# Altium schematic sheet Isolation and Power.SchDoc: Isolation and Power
size A3; CompanyName: Hitex GmbH; Address1: Greschbachstr. 12; Address2: 76229 Karlsruhe, Germany; Address3: www.hitex.com; DocumentNumber: 6; SheetNumber: 6; SheetTotal: 8; PageSetup: Record=PageOptions¦CenterHorizontal=True¦CenterVertical=True¦PrintScale=1.04¦XCorrection=1.00¦YCorrection=1.00¦PrintKind=0¦BorderSize=5000000¦LeftOffset=0¦BottomOffset=0¦Orientation=2¦PaperLength=1000¦PaperWidth=1000¦Scale=100¦PaperSource=7¦PrintQuality=1200¦MediaType=1¦DitherType=10¦PaperKind=A3¦PrintScaleMode=1
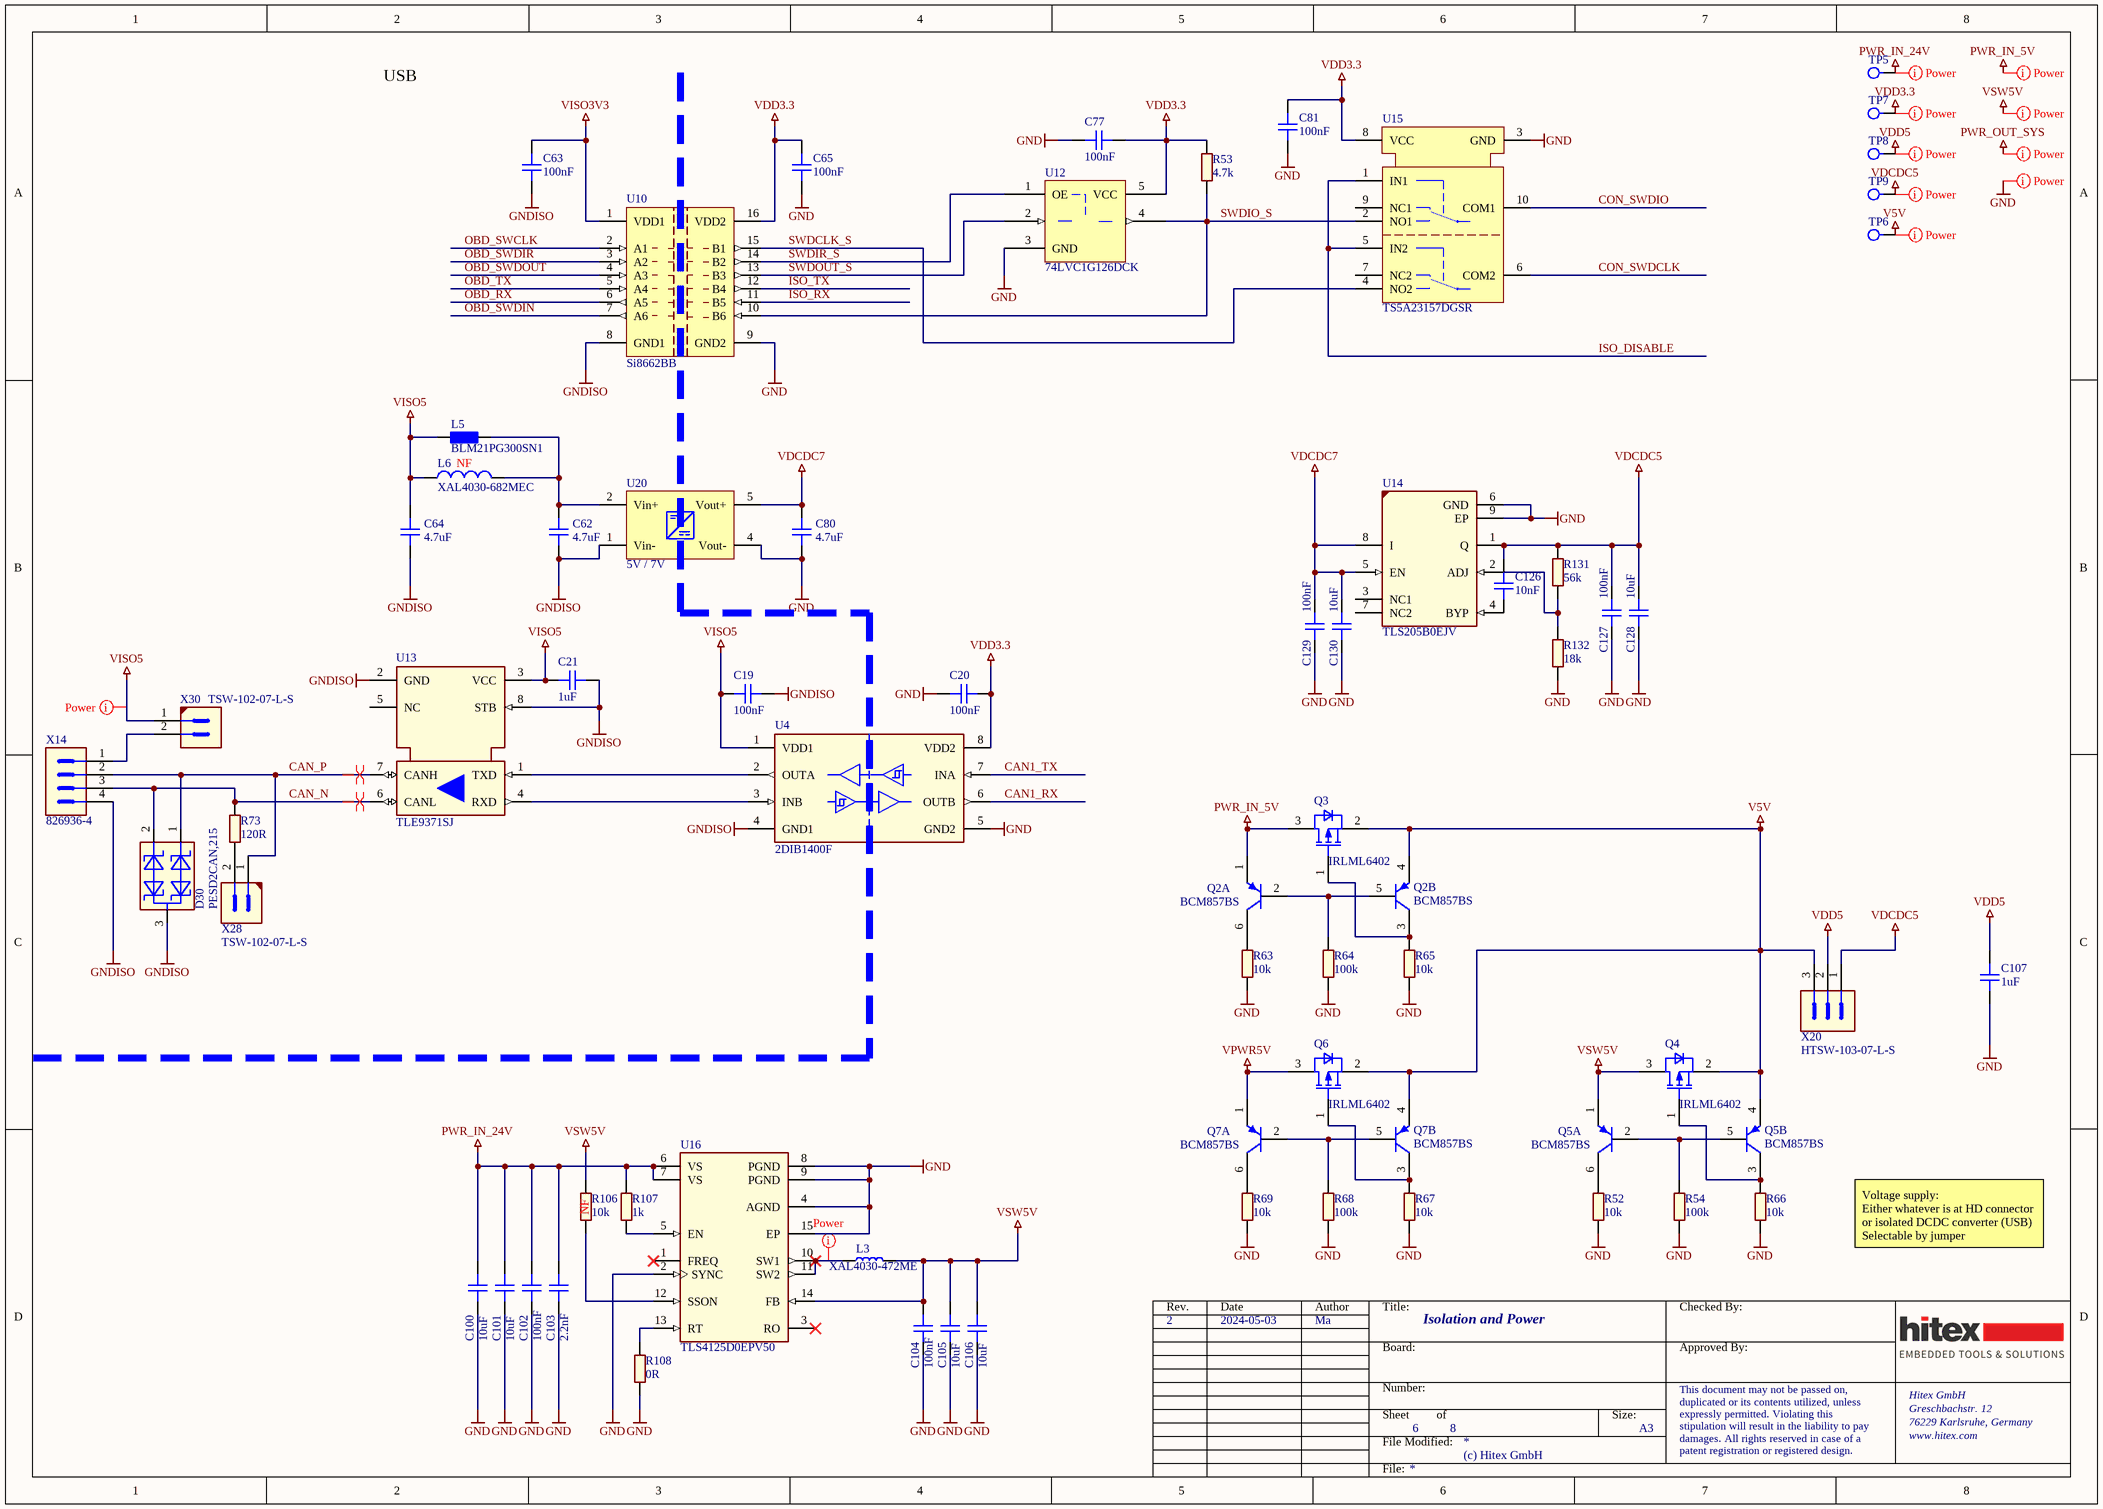
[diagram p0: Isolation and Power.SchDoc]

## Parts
C19  100nF  [CAPC1005X55N-0]
C20  100nF  [CAPC1005X55N-0]
C21  1uF  [CAPC1608X90N-1]
C62  4.7uF  [CAPC2013X145N-3]
C63  100nF  [CAPC1005X55N-0]
C64  4.7uF  [CAPC2013X145N-3]
C65  100nF  [CAPC1005X55N-0]
C77  100nF  [CAPC1005X55N-0]
C80  4.7uF  [CAPC2013X145N-3]
C81  100nF  [CAPC1005X55N-0]
C100  10uF  [CAPC3216X180N]
C101  10uF  [CAPC3216X180N]
C102  100nF  [CAPC1005X55N-0]
C103  2.2nF  [CAPC1005X55N-0]
C104  100nF  [CAPC1005X55N-0]
C105  10uF  [CAPC3216X180N]
C106  10uF  [CAPC3216X180N]
C107  1uF  [CAPC1608X90N-1]
C126  10nF  [CAPC1005X55N-0]
C127  100nF  [CAPC1005X60N]
C128  10uF  [CAPC3216X180N]
C129  100nF  [CAPC1005X55N-0]
C130  10uF  [CAPC3216X180N]
D30  PESD2CAN,215  [SOT95P230X110-3N]
L3  4.7uH  [XAL4030-472ME]  (value not drawn)
L5  BLM21PG300SN1  [INDC2009N]
L6  XAL4030-682MEC  [XFL4020]
Q2  BCM857BS  [SOT363-6M]  (parts A,B of 2)
Q3  IRLML6402  [SOT95P237X112-3N-2-V]
Q4  IRLML6402  [SOT95P237X112-3N-2-V]
Q5  BCM857BS  [SOT363-6M]  (parts A,B of 2)
Q6  IRLML6402  [SOT95P237X112-3N-2-V]
Q7  BCM857BS  [SOT363-6M]  (parts A,B of 2)
R52  10k  [RESC1005X40N]
R53  4.7k  [RESC1609X50N]
R54  100k  [RESC1005X40N]
R63  10k  [RESC1005X40N]
R64  100k  [RESC1005X40N]
R65  10k  [RESC1005X40N]
R66  10k  [RESC1005X40N]
R67  10k  [RESC1005X40N]
R68  100k  [RESC1005X40N]
R69  10k  [RESC1005X40N]
R73  120R  [RESC3216X60N]
R106  10k  [RESC1005X40N]
R107  1k  [RESC1005X40N]
R108  0R  [RESC1005X03N]
R131  56k  [RESC1005X40N]
R132  18k  [RESC1005X40N]
TP5  (no value)  [TP_RD_SMD_1MM]  (no BOM)
TP6  (no value)  [TP_RD_SMD_1MM]  (no BOM)
TP7  (no value)  [TP_RD_SMD_1MM]  (no BOM)
TP8  (no value)  [TP_RD_SMD_1MM]  (no BOM)
TP9  (no value)  [TP_RD_SMD_1MM]  (no BOM)
U4  2DIB1400F  [SOIC127P600X175-8N-22-V1]
U10  Si8662BB  [SOIC127P600-16N]
U12  74LVC1G126DCK  [SOT353-5N]
U13  TLE9371SJ  [SOIC127P602X173-8N]
U14  TLS205B0EJV  [SOIC127P600X170-9N-3-V1]
U15  TS5A23157DGSR  [VSSOP50P490X110-10N]
U16  TLS4125D0EPV50  [SOP65P600X115-15N]
U20  5V / 7V  [IES0205S05]
X14  826936-4  [CON-M-THT-826936-4]
X20  HTSW-103-07-L-S  [CON-M-THT-HTSW-103-07-L-S]
X28  TSW-102-07-L-S  [CON-M-THT-TSW-102-07-L-S]
X30  TSW-102-07-L-S  [CON-M-THT-TSW-102-07-L-S]

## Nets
GND: C20.2 C65.1 C77.1 C80.1 C81.1 C100.1 C101.1 C102.2 C103.1 C104.1 C105.1 C106.1 C107.1 C127.1 C128.1 C129.1 C130.1 R52.1 R54.2 R63.1 R64.2 R65.1 R66.1 R67.1 R68.2 R69.1 R108.1 R132.1 U4.5(GND2) U10.9(GND2) U12.3(GND) U14.6(GND) U14.9(EP) U15.3(GND) U16.2(SYNC) U16.4(AGND) U16.8(PGND) U16.9(PGND) U16.15(EP) U20.4(Vout-)
GNDISO: C19.2 C21.1 C62.1 C63.1 C64.1 D30.3(COMMON_CATHODE) U4.4(GND1) U10.8(GND1) U13.2(GND) U13.8(STB) U20.1(Vin-) X14.4
PWR_IN_5V: Q2.1(E1) Q3.3(DRAIN)
PWR_IN_24V: C100.2 C101.2 C102.1 C103.2 R107.2 TP5.1 U16.6(VS) U16.7(VS)
V5V: Q2.4(E2) Q3.2(SOURCE) Q4.2(SOURCE) Q5.4(E2) Q6.2(SOURCE) Q7.4(E2) TP6.1 X20.3
VDCDC5: C126.2 C127.2 C128.2 R131.2 TP9.1 U14.1(Q) X20.1
VDCDC7: C80.2 C129.2 C130.2 U14.5(EN) U14.8(I) U20.5(Vout+)
VDD3.3: C20.1 C65.2 C77.2 C81.2 R53.2 TP7.1 U4.8(VDD2) U10.16(VDD2) U12.5(VCC) U15.8(VCC)
VDD5: C107.2 TP8.1 X20.2
VISO3V3: C63.2 U10.1(VDD1)
VISO5: C19.1 C21.2 C64.2 L5.1 L6.1 U4.1(VDD1) U13.3(VCC) X30.1
VPWR5V: Q6.3(DRAIN) Q7.1(E1)
VSW5V: C104.2 C105.2 C106.2 L3.2 Q4.3(DRAIN) Q5.1(E1) R106.2 U16.14(FB)
CAN1_RX: U4.6(OUTB)
CAN1_TX: U4.7(INA)
CAN_N: D30.2(CATHODE2) R73.2 U13.6(CANL) X14.3
CAN_P: D30.1(CATHODE1) U13.7(CANH) X14.2 X28.1
CON_SWDCLK: U15.6(COM2)
CON_SWDIO: U15.10(COM1)
ISO_DISABLE: U15.1(IN1) U15.5(IN2)
ISO_RX: U10.11(B5)
ISO_TX: U10.12(B4)
OBD_RX: U10.6(A5)
OBD_SWCLK: U10.2(A1)
OBD_SWDIN: U10.7(A6)
OBD_SWDIR: U10.3(A2)
OBD_SWDOUT: U10.4(A3)
OBD_TX: U10.5(A4)
SWDCLK_S: U10.15(B1) U15.4(NO2)
SWDIO_S: R53.1 U10.10(B6) U12.4(Y) U15.2(NO1)
SWDIR_S: U10.14(B2) U12.1(OE)
SWDOUT_S: U10.13(B3) U12.2(A)
NetC62_2: C62.2 L5.2 L6.2 U20.2(Vin+)
NetC126_1: C126.1 U14.4(BYP)
NetL3_1: L3.1 U16.10(SW1) U16.11(SW2)
NetQ2_2: Q2.2(B1) Q2.5(B2) R64.1
NetQ2_3: Q2.3(C2) Q3.1(GATE) R65.2
NetQ2_6: Q2.6(C1) R63.2
NetQ4_1: Q4.1(GATE) Q5.3(C2) R66.2
NetQ5_2: Q5.2(B1) Q5.5(B2) R54.1
NetQ5_6: Q5.6(C1) R52.2
NetQ6_1: Q6.1(GATE) Q7.3(C2) R67.2
NetQ7_2: Q7.2(B1) Q7.5(B2) R68.1
NetQ7_6: Q7.6(C1) R69.2
NetR73_1: R73.1 X28.2
NetR106_1: R106.1 U16.12(SSON)
NetR107_1: R107.1 U16.5(EN)
NetR108_2: R108.2 U16.13(RT)
NetR131_1: R131.1 R132.2 U14.2(ADJ)
NetU4_2: U4.2(OUTA) U13.1(TXD)
NetU4_3: U4.3(INB) U13.4(RXD)
NetX14_1: X14.1 X30.2

Not connected (* = marked no-connect by the designer): U13 5(NC); U14 3(NC1) 7(NC2); U15 7(NC2) 9(NC1); U16 1(FREQ)* 3(RO)*

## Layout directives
net class Power: GND, NetL3_1, PWR_IN_5V, PWR_IN_24V, PWR_OUT_SYS, V5V, VDCDC5, VDD3.3, VDD5, VISO5, VSW5V
differential pair; differential pair class DIFF120R: CAN_N, CAN_P

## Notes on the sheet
- USB
- (near L6) NF
- (near R106) NF
- Voltage supply:
  Either whatever is at HD connector
  or isolated DCDC converter (USB)
  Selectable by jumper
- 2
- 2024-05-03
- Ma
- Labels drawn without touching a wire or pin: GND, PWR_IN_5V, PWR_OUT_SYS, VSW5V

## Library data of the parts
C19 C20 C63 C65 C77 C81 C102 C104 C129 = 310625: CAP / CERA / 100nF / 50V / 10% / X7R (EIA) / -55°C to 125°C / 0402(1005) / SMD / -; Multiple Parts: No; Legacy PartNumber: CAP01010920; Manufacturer: MuRata; Manufacturer Order Number: GRM155R71H104KE14D; Symbol Type: Capacitor; Single; Standard; 2 Pins; Alternate View: Yes; Article Number: 310625; Version Number: V01; Combined Parameters: TC:X7R (EIA);Tol.:-10%/+10%;Vdc:50V; QuickPick: 100nF / 50V / 10% / X7R (EIA) / 0402 (1005M); Type: Standard; Style: Single; Package Metric: 1005; Package Imperial: 0402; ComponentStatus: Released; PLMStatus: Active; HTX: 01.22.0596.0
C21 C107 = 668123: CAP / CERA / 1uF / 25V / 10% / X7R (EIA) / -55°C to 125°C / 0603(1608) / SMD / -; Multiple Parts: No; Manufacturer: Samsung; Manufacturer Order Number: CL10B105KA8NNNC; Symbol Type: Capacitor; Single; Standard; 2 Pins; Alternate View: Yes; Article Number: 668123; Version Number: V01; Combined Parameters: TC:X7R (EIA);Tol.:-10%/+10%;Vdc:25V; QuickPick: 1uF / 25V / 10% / X7R (EIA) / 0603 (1608); Type: Standard; Style: Single; Package Metric: 1608; Package Imperial: 0603; ComponentStatus: Released; PLMStatus: Active; HTX: 01.22.0270.0
C62 C64 C80 = 673682: CAP / CERA / 4.7uF / 25V / 20% / X7R (EIA) / -55°C to 125°C / 0805 / SMD / -; Multiple Parts: No; Manufacturer: Yageo; Manufacturer Order Number: CC0805MKX7R8BB475; Symbol Type: Capacitor; Single; Standard; 2 Pins; Alternate View: Yes; Article Number: 673682; Version Number: V00; Combined Parameters: TC:X7R (EIA);Tol.:-20%/+20%;Vdc:25V; QuickPick: 4.7uF / 25V / 20% / X7R (EIA) / 0805; Type: Standard; Style: Single; ComponentStatus: Released; PLMStatus: Active; HTX: 01.22.0436.0
C100 C101 C105 C106 C128 C130 = 282249: CAP / CERA / 10uF / 50V / 20% / X5R (EIA) / -55°C to 85°C / 1206(3216) / SMD / -; Multiple Parts: No; Manufacturer: MuRata; Manufacturer Order Number: GRM31CR61H106MA12L; Symbol Type: Capacitor; Single; Standard; 2 Pins; Alternate View: Yes; Article Number: 282249; Version Number: V01; Combined Parameters: TC:X5R (EIA);Tol.:-20%/+20%;Vdc:50V; QuickPick: 10uF / 50V / 20% / X5R (EIA) / 1206 (3216); Type: Standard; Style: Single; Package Metric: 3216; Package Imperial: 1206; ComponentStatus: Released; PLMStatus: Not Recommended For New Designs; HTX: 01.22.0647.0
C103 = 289386: CAP / CERA / 2.2nF / 50V / 20% / X7R (EIA) / -55°C to 125°C / 0402(1005) / SMD / -; Multiple Parts: No; Legacy PartNumber: CAP01006950; Manufacturer: MuRata; Manufacturer Order Number: GCM155R71H222MA37; Symbol Type: Capacitor; Single; Standard; 2 Pins; Alternate View: Yes; Article Number: 289386; Version Number: V01; Combined Parameters: TC:X7R (EIA);Tol.:-20%/+20%;Vdc:50V; QuickPick: 2.2nF / 50V / 20% / X7R (EIA) / CAPC1005X55N-0; Type: Standard; Style: Single; Automotive Qualified: AEC Q200; Package Metric: 1005; Package Imperial: 0402; ComponentStatus: Released; PLMStatus: Active; HTX: 01.22.0627.0
C126 = 264563: CAP / CERA / 10nF / 16V / 5% / X7R (EIA) / -55°C to 125°C / 0402(1005) / SMD / -; Multiple Parts: No; Legacy PartNumber: CAP01001706; Manufacturer: MuRata; Manufacturer Order Number: GRM155R71C103JA01; Symbol Type: Capacitor; Single; Standard; 2 Pins; Alternate View: Yes; Article Number: 264563; Version Number: V01; Combined Parameters: TC:X7R (EIA);Tol.:-5%/+5%;Vdc:16V; QuickPick: 10nF / 16V / 5% / X7R (EIA) / 0402 (1005); Type: Standard; Style: Single; Package Metric: 1005; Package Imperial: 0402; ComponentStatus: Released; PLMStatus: Not Recommended For New Designs; HTX: 01.22.0592.0
C127 = 507459: CAP / CERA / 100nF / 50V / 10% / X7R (EIA) / -55°C to 125°C / 0402(1005) / SMD / -; Multiple Parts: No; Manufacturer: TDK Corporation; Manufacturer Order Number: C1005X7R1H104K050BE; Symbol Type: Capacitor; Single; Standard; 2 Pins; Alternate View: Yes; Article Number: 507459; Version Number: V01; Combined Parameters: TC:X7R (EIA);Tol.:-10%/+10%;Vdc:50V; QuickPick: 100nF / 50V / 10% / X7R (EIA) / 0402 (1005); Type: Standard; Style: Single; Package Metric: 1005; Package Imperial: 0402; ComponentStatus: Released; PLMStatus: Active; HTX: 01.22.0596.0
D30 = 527432: CAN bus ESD protection diode; Multiple Parts: No; Manufacturer: Nexperia; Symbol type: Bi-Directional Transient Voltage Suppressor Diode, 1 Cathode 2 Cathode 3 Common Cathode; Article Number: 527432; Version Number: V01; Combined Parameters: Vf:-;If:-;Ur:24V;Ir:-;Pmax:-; QuickPick: TVS Diode / SOT23 (TO-236AB); Type: TVS Diode; Style: Single; Automotive Qualified: AEC Q101; ComponentStatus: Released; PLMStatus: Active; Second Source allowed: Yes; Voltage DC (max): na; HTX: 00.40.0090.0
L3 = 325876: IND / STD / 4.7uH / 5.1A / 20% / -40°C to 125°C / 44.1R / SMD Type / Inductor,Chip;4.00mm L X 4.00mm W X 3.10mm H / SMD / -; Multiple Parts: No; Legacy PartNumber: IND00702665; Manufacturer: Coilcraft; Symbol Type: Inductor; Single; Standard; 2 Pins; Alternate View: Yes; Article Number: 325876; Version Number: V01; Combined Parameters: Tol.:-20%/+20%;Rdc:44.1R;Idc:5.1A;Fres:36MHz; QuickPick: 4.7uH / Standard / SMD Type; Type: Standard; Style: Single; Automotive Qualified: AEC Q200; ComponentStatus: Released; PLMStatus: Active; Voltage DC (max): na; HTX: 01.30.0268.0
L5 = BLM21PG300SN1: FERRITE, SMD, 30 OHM, 4000mA, 0805; PartNumber: 01.30.0266.0; Manufacturer: Murata; Designer: Ma; CheckOrientation: false
L6 = XAL4030-682MEC: 2.2uH - Isat 5.6A; PartNumber: 01.30.0326.0; Manufacturer: Coilcraft; Designer: Kr; CheckOrientation: false
Q2 Q5 Q7 = BCM8575BS,115: Dual PNP/PNP, Vceo -45V, Ic -100mA, hFE 290, AEC-Q; PartNumber: 00.94.0374.0; Manufacturer: Nexperia; ManufacturerPartNo: BCM857BS,115; Designer: Th; CheckOrientation: ´True
Q3 Q4 Q6 = 400833: HEXFET P-Channel Power MOSFET, 20V, 3.7A; Manufacturer: Infineon Technologies; Symbol Type: Insulated-Gate Field-Effect Transistor (IGFET), P-Channel, Enhancement,  Body Diode, Pin 1 Gate, 2 Source, 3 Drain, 3 Pins; Article Number: 400833; Version Number: V01; Legacy DeviceID: IFX_IRLML6402; Combined Parameters: P-Channel;Uds:-20V;Id:-3.7A;Rds:65mR;P:1.3W; QuickPick: P-Channel / 1.3W / -3.7A / -20V / PG-SOT23-3-901; Style: Single; Automotive Qualified: No; ComponentStatus: Released; PLMStatus: Active; Second Source allowed: Yes; Voltage DC (max): na; HTX: 00.94.0102.0
R52 R63 R65-R67 R69 R106 = 342167: RES / STD / 10k / 63mW / 1% / 100ppm/K / -55°C to 155°C / 0402 / SMD / -; Multiple Parts: No; Legacy PartNumber: RES01800457; Manufacturer: Vishay; Manufacturer Order Number: CRCW040210K0FK; Symbol Type: Resistor; Single; Standard; 2 Pins; Alternate View: Yes; Article Number: 342167; Version Number: V01; Combined Parameters: TCR:100ppm/K;Tol.:-1%/+1%;Vdc:50V;Idc:-;P:63mW; QuickPick: 10k / 1% / 0.063 / 0402; Style: Single; Automotive Qualified: AEC Q200; ComponentStatus: Released; PLMStatus: Active; Voltage DC (max): 50V; HTX: 01.02.0703.0
R53 = 345982: RES / STD / 4.7k / 100mW / 1% / 100ppm/K / -55°C to 155°C / 0603(1608) / SMD / -; Multiple Parts: No; Legacy PartNumber: RES01801219; Manufacturer: Vishay; Manufacturer Order Number: CRCW06034K70FK; Symbol Type: Resistor; Single; Standard; 2 Pins; Alternate View: Yes; Article Number: 345982; Version Number: V01; Combined Parameters: TCR:100ppm/K;Tol.:-1%/+1%;Vdc:75V;Idc:-;P:100mW; QuickPick: 4.7k / 1% / 0.1 / 0603 (1608); Style: Single; Automotive Qualified: AEC Q200; Package Metric: 1608; Package Imperial: 0603; ComponentStatus: Released; PLMStatus: Active; Voltage DC (max): 75V; HTX: 01.02.0437.0
R54 R64 R68 = 342737: RES / STD / 100k / 63mW / 1% / 100ppm/K / -55°C to 155°C / 0402 / SMD / -; Multiple Parts: No; Legacy PartNumber: RES01800571; Manufacturer: Vishay; Manufacturer Order Number: CRCW0402100KFK; Symbol Type: Resistor; Single; Standard; 2 Pins; Alternate View: Yes; Article Number: 342737; Version Number: V01; Combined Parameters: TCR:100ppm/K;Tol.:-1%/+1%;Vdc:50V;Idc:-;P:63mW; QuickPick: 100k / 1% / 0.063 / 0402; Style: Single; Automotive Qualified: AEC Q200; ComponentStatus: Released; PLMStatus: Active; Voltage DC (max): 50V; HTX: 01.02.0716.0
R73 = 353082: RES / STD / 120R / 250mW / 1% / 100ppm/K / -55°C to 155°C / 1206(3216) / SMD / -; Multiple Parts: No; Legacy PartNumber: RES01802637; Manufacturer: Vishay; Manufacturer Order Number: CRCW1206120RFK; Symbol Type: Resistor; Single; Standard; 2 Pins; Alternate View: Yes; Article Number: 353082; Version Number: V01; Combined Parameters: TCR:100ppm/K;Tol.:-1%/+1%;Vdc:200V;Idc:-;P:250mW; QuickPick: 120R / 1% / 0.25 / 1206 (3216); Style: Single; Automotive Qualified: AEC Q200; Package Metric: 3216; Package Imperial: 1206; ComponentStatus: Released; PLMStatus: Active; Voltage DC (max): 200V; HTX: 01.02.0102.0
R107 = 341597: RES / STD / 1k / 63mW / 1% / 100ppm/K / -55°C to 155°C / 0402 / SMD / -; Multiple Parts: No; Legacy PartNumber: RES01800343; Manufacturer: Vishay; Manufacturer Order Number: CRCW04021K00FK; Symbol Type: Resistor; Single; Standard; 2 Pins; Alternate View: Yes; Article Number: 341597; Version Number: V01; Combined Parameters: TCR:100ppm/K;Tol.:-1%/+1%;Vdc:50V;Idc:-;P:63mW; QuickPick: 1k / 1% / 0.063 / 0402; Style: Single; Automotive Qualified: AEC Q200; ComponentStatus: Released; PLMStatus: Active; Voltage DC (max): 50V; HTX: 01.02.0701.0
R108 = 327372: RES / STD / 0R / 63mW / 0R / 0ppm/K / -55°C to 155°C / 0402(1005) / SMD / -; Multiple Parts: No; Legacy PartNumber: RES00000001; Manufacturer: Yageo; Manufacturer Order Number: RC0402JR-070RL; Symbol Type: Resistor; Single; Standard; 2 Pins; Alternate View: Yes; Article Number: 327372; Version Number: V01; Combined Parameters: TCR:0ppm/K;Tol.:-0R/+0R;Vdc:50V;Idc:1A;P:63mW; QuickPick: 0R / 0R / 0.063 / 0402 (1005); Style: Single; Package Metric: 1005; Package Imperial: 0402; ComponentStatus: Released; PLMStatus: Active; Voltage DC (max): 50V; HTX: 01.02.0902.0
R131 = 342592: RES / STD / 56k / 63mW / 1% / 100ppm/K / -55°C to 155°C / 0402(1005) / SMD / -; Multiple Parts: No; Legacy PartNumber: RES01800542; Manufacturer: Vishay; Manufacturer Order Number: CRCW040256K0FK; Symbol Type: Resistor; Single; Standard; 2 Pins; Alternate View: Yes; Article Number: 342592; Version Number: V01; Combined Parameters: TCR:100ppm/K;Tol.:-1%/+1%;Vdc:50V;Idc:-;P:63mW; QuickPick: 56k / 1% / 0.063 / 0402 (1005); Style: Single; Automotive Qualified: AEC Q200; Package Metric: 1005; Package Imperial: 0402; ComponentStatus: Released; PLMStatus: Active; Voltage DC (max): 50V; HTX: 01.02.0770.0
R132 = 342302: RES / STD / 18k / 63mW / 1% / 100ppm/K / -55°C to 155°C / 0402(1005) / SMD / -; Multiple Parts: No; Legacy PartNumber: RES01800484; Manufacturer: Vishay; Manufacturer Order Number: CRCW040218K0FK; Symbol Type: Resistor; Single; Standard; 2 Pins; Alternate View: Yes; Article Number: 342302; Version Number: V01; Combined Parameters: TCR:100ppm/K;Tol.:-1%/+1%;Vdc:50V;Idc:-;P:63mW; QuickPick: 18k / 1% / 0.063 / 0402 (1005); Style: Single; Automotive Qualified: AEC Q200; Package Metric: 1005; Package Imperial: 0402; ComponentStatus: Released; PLMStatus: Active; Voltage DC (max): 50V; HTX: 01.02.0757.0
TP5-TP9 = Testpad_Round: Testpad SMD / THT; PartNumber: -NoPartNumber-; Designer: Ma; CheckOrientation: false
U4 = 2DIB1400F: Robust Digital Isolator, 1 Forward 1 Reverse Channel Configuration; Manufacturer: Infineon Technologies; HTX: 00.81.0361.0
U10 = Si8662BB-B-IS1: 6-Ch Digital Isolator (4xIn / 2xOut), 150Mbit/s, 2500Vrms, SOIC-16, active low; Manufacturer: Skyworks Solutions Inc.; PartNumber: 00.81.0252.0; Designer: Ma; CheckOrientation: true
U12 = 74LVC1G126DCK: Single Gate Buffer/Driver, OE high active, 1.65V - 5.5V, SC70-5; PartNumber: 00.29.0112.0; Manufacturer: Texas Instruments; ManufacturerPartNo: SN74LVC1G126DCKR; Designer: Ma; Note: NXP 74LVC1G126GW; CheckOrientation: false
U13 = 694499: CAN signal improvement transceiver; Manufacturer: Infineon Technologies; Alternate View: No; Symbol Type: High Speed CAN FD Transceiver; Article Number: 694499; Version Number: V01; Legacy DeviceID: IFX_TLE9371SJ; Combined Parameters: Automotive Interface/Transceiver;Vdc min/max:4.75V/5.25V;Iout:5mA;Fmax:-; QuickPick: PG-DSO-8-80; Automotive Qualified: AEC Q100; ComponentStatus: Released; PLMStatus: Active; Second Source allowed: Yes; Voltage DC (max): na; HTX: 00.40.0396.0
U14 = 592428: Micropower, low noise, low dropout voltage regulator, Designed for use in battery-powered systems, the low quiescent current of 30 µA makes it an ideal choice; Multiple Parts: No; Manufacturer: Infineon Technologies; Symbol Type: Low Dropout, Low Noise, Linear Voltage Post Regulator, 3.3V, 500 mA; Article Number: 592428; Version Number: V01; Legacy DeviceID: IFX_TLS205B0EJV; Combined Parameters: Linear - -;Vo:1.19V to 1.25V; QuickPick: Linear / PG-DSO-8-52; Automotive Qualified: Yes; ComponentStatus: Released; PLMStatus: Active; Voltage DC (max): na; HTX: 00.40.0359.0
U15 = TS5A23157DGSR: TS5A23157DGSR, 1.8V-5V, 2:1 (SPDT), 2-channel analog switch, 10R; PartNumber: 00.30.0133.0; Manufacturer: Texas Instruments; Designer: Th; CheckOrientation: true
U16 = 513815: OPTIREG Switcher 2.8 MHz Synchronous Step-Down Regulator, 2.5A, 5V, Input voltage 3.7 V to 35 V; Manufacturer: Infineon Technologies; Alternate View: No; Article Number: 513815; Version Number: V01; Legacy DeviceID: IFX_TLS4125D0EPV50; Combined Parameters: Switched DC/DC -;Vo:- to 5V; QuickPick: Switched / PG-TSDSO-14-5; Style: DC/DC; Automotive Qualified: AEC Q100/Q101; ComponentStatus: Released; PLMStatus: Active; Second Source allowed: Yes; Voltage DC (max): na; HTX: 00.97.0363.0
U20 = IES0205S07: Isolated DC/DC Converter, 5V/7V, 286mA, 2W, SMD, 3kV Iso, unregulated; Manufacturer: XP Power; Designer: Ma; CheckOrientation: true; HTX: 00.97.0434.0
X14 = 378014: Header, THT, Single Row, Vertical, 2.54mm, 4 Pins; Manufacturer: TE Connectivity; Article Number: 378014; Version Number: V01; Legacy DeviceID: TE_826936-4; Combined Parameters: Board-to-Board Header (male);4x1;Mounting:THT;Orient:0° (vertical);Shielded:-; QuickPick: 0° (vertical) / Board-to-Board; Style: Strip; Automotive Qualified: No; ComponentStatus: Released; PLMStatus: Active; Second Source allowed: Yes; Voltage DC (max): na; HTX: 03.20.0003.0
X20 = 378477: Through hole .025 SQ Post Header, 2.54mm pitch, 3 pin, vertical, single row; Legacy PartNumber: CON01500137; Manufacturer: Samtec; Article Number: 378477; Version Number: V01; Legacy DeviceID: SAM_HTSW-103-07-L-S; Combined Parameters: Board-to-Board Header (male);3x1;Mounting:THT;Orient:0° (vertical);Shielded:No; QuickPick: 0° (vertical) / Board-to-Board; Style: Strip; Automotive Qualified: No; ComponentStatus: Released; PLMStatus: Active; Second Source allowed: Yes; Voltage DC (max): na; HTX: 03.20.0002.0
X28 X30 = 382904: Through hole .025 SQ Post Header, 2.54mm pitch, 2 pin, vertical, single row; Legacy PartNumber: CON01500574; Manufacturer: Samtec; Alternat View: Yes; Article Number: 382904; Version Number: V01; Legacy DeviceID: SAM_TSW-102-07-L-S; Combined Parameters: Board-to-Board Header (male);2x1;Mounting:THT;Orient:0° (vertical);Shielded:No; QuickPick: 0° (vertical) / Board-to-Board; Style: Strip; Automotive Qualified: No; ComponentStatus: Released; PLMStatus: Active; Voltage DC (max): na; HTX: 03.20.0001.0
